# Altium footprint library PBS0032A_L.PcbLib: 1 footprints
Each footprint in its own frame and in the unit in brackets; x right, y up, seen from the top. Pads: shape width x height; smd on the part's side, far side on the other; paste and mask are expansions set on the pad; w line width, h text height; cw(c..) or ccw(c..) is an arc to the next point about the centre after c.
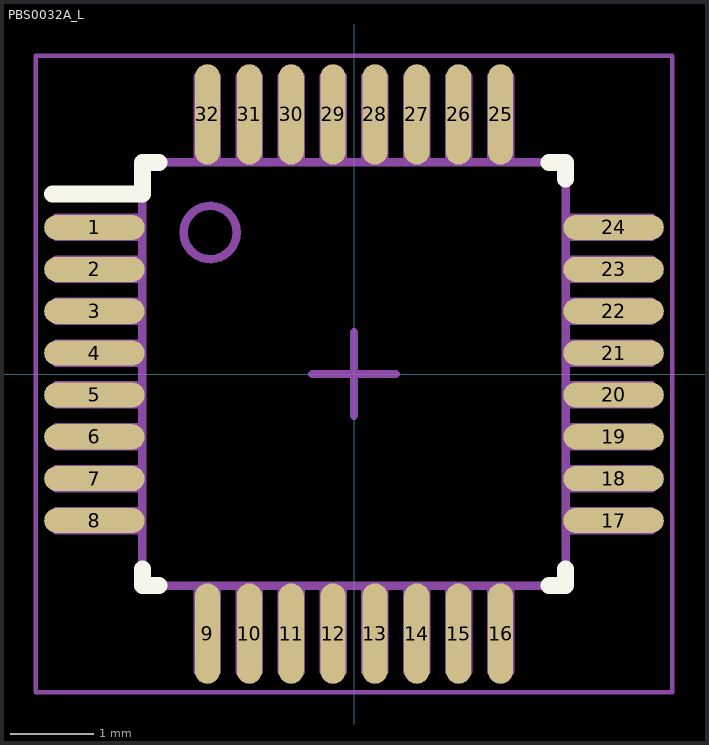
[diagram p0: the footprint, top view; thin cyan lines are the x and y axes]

## PBS0032A_L [mm]
height 1.2
pads (32):
  oval 1.2x0.3 smd: 1(-3.1,1.75) 2(-3.1,1.25) 3(-3.1,0.75) 4(-3.1,0.25) 5(-3.1,-0.25) 6(-3.1,-0.75) 7(-3.1,-1.25) 8(-3.1,-1.75) 17(3.1,-1.75) 18(3.1,-1.25) 19(3.1,-0.75) 20(3.1,-0.25) 21(3.1,0.25) 22(3.1,0.75) 23(3.1,1.25) 24(3.1,1.75)
  oval 0.3x1.2 smd: 9(-1.75,-3.1) 10(-1.25,-3.1) 11(-0.75,-3.1) 12(-0.25,-3.1) 13(0.25,-3.1) 14(0.75,-3.1) 15(1.25,-3.1) 16(1.75,-3.1) 25(1.75,3.1) 26(1.25,3.1) 27(0.75,3.1) 28(0.25,3.1) 29(-0.25,3.1) 30(-0.75,3.1) 31(-1.25,3.1) 32(-1.75,3.1)
Top Overlay:
  lines w0.2: -3.6,2.15 -2.527,2.15 -2.527,2.527 -2.327,2.527 ; -2.527,-2.327 -2.527,-2.527 -2.327,-2.527 ; 2.327,-2.527 2.527,-2.527 2.527,-2.327 ; 2.327,2.527 2.527,2.527 2.527,2.327
Mechanical 5:
  circle w0.1: c-1.718,1.69 r0.318
  lines w0.1: -3.556,-1.864 -3.556,-1.636 -2.527,-1.636 -2.527,-1.864 -3.556,-1.864 ; -3.556,-1.364 -3.556,-1.136 -2.527,-1.136 -2.527,-1.364 -3.556,-1.364 ; -3.556,-0.864 -3.556,-0.636 -2.527,-0.636 -2.527,-0.864 -3.556,-0.864 ; -3.556,-0.364 -3.556,-0.136 -2.527,-0.136 -2.527,-0.364 -3.556,-0.364 ; -3.556,0.136 -3.556,0.364 -2.527,0.364 -2.527,0.136 -3.556,0.136 ; -3.556,0.636 -3.556,0.864 -2.527,0.864 -2.527,0.636 -3.556,0.636 ; -3.556,1.136 -3.556,1.364 -2.527,1.364 -2.527,1.136 -3.556,1.136 ; -3.556,1.636 -3.556,1.864 -2.527,1.864 -2.527,1.636 -3.556,1.636 ; -2.527,-2.527 2.527,-2.527 2.527,2.527 -2.527,2.527 -2.527,-2.527 ; -1.864,-3.556 -1.864,-2.527 -1.636,-2.527 -1.636,-3.556 -1.864,-3.556 ; -1.864,2.527 -1.636,2.527 -1.636,3.556 -1.864,3.556 -1.864,2.527 ; -1.364,-3.556 -1.364,-2.527 -1.136,-2.527 -1.136,-3.556 -1.364,-3.556 ; -1.364,2.527 -1.136,2.527 -1.136,3.556 -1.364,3.556 -1.364,2.527 ; -0.864,-3.556 -0.864,-2.527 -0.636,-2.527 -0.636,-3.556 -0.864,-3.556 ; -0.864,2.527 -0.636,2.527 -0.636,3.556 -0.864,3.556 -0.864,2.527 ; -0.364,-3.556 -0.364,-2.527 -0.136,-2.527 -0.136,-3.556 -0.364,-3.556 ; -0.364,2.527 -0.136,2.527 -0.136,3.556 -0.364,3.556 -0.364,2.527 ; 0.136,-3.556 0.136,-2.527 0.364,-2.527 0.364,-3.556 0.136,-3.556 ; 0.136,2.527 0.364,2.527 0.364,3.556 0.136,3.556 0.136,2.527 ; 0.636,-3.556 0.636,-2.527 0.864,-2.527 0.864,-3.556 0.636,-3.556 ; 0.636,2.527 0.864,2.527 0.864,3.556 0.636,3.556 0.636,2.527 ; 1.136,-3.556 1.136,-2.527 1.364,-2.527 1.364,-3.556 1.136,-3.556 ; 1.136,2.527 1.364,2.527 1.364,3.556 1.136,3.556 1.136,2.527 ; 1.636,-3.556 1.636,-2.527 1.864,-2.527 1.864,-3.556 1.636,-3.556 ; 1.636,2.527 1.864,2.527 1.864,3.556 1.636,3.556 1.636,2.527 ; 2.527,-1.864 2.527,-1.636 3.556,-1.636 3.556,-1.864 2.527,-1.864 ; 2.527,-1.364 2.527,-1.136 3.556,-1.136 3.556,-1.364 2.527,-1.364 ; 2.527,-0.864 2.527,-0.636 3.556,-0.636 3.556,-0.864 2.527,-0.864 ; 2.527,-0.364 2.527,-0.136 3.556,-0.136 3.556,-0.364 2.527,-0.364 ; 2.527,0.136 2.527,0.364 3.556,0.364 3.556,0.136 2.527,0.136 ; 2.527,0.636 2.527,0.864 3.556,0.864 3.556,0.636 2.527,0.636 ; 2.527,1.136 2.527,1.364 3.556,1.364 3.556,1.136 2.527,1.136 ; 2.527,1.636 2.527,1.864 3.556,1.864 3.556,1.636 2.527,1.636
  text ".Designator" at -1.98,-0.54 h1.1
Mechanical 15:
  lines w0.05: -3.8,-3.8 3.8,-3.8 3.8,3.8 -3.8,3.8 -3.8,-3.8
  lines w0.1: -0.5,0 0.5,0 ; 0,-0.5 0,0.5
3D body: height 1.2, standoff 0, extent -3.505,-3.505 3.506,3.506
